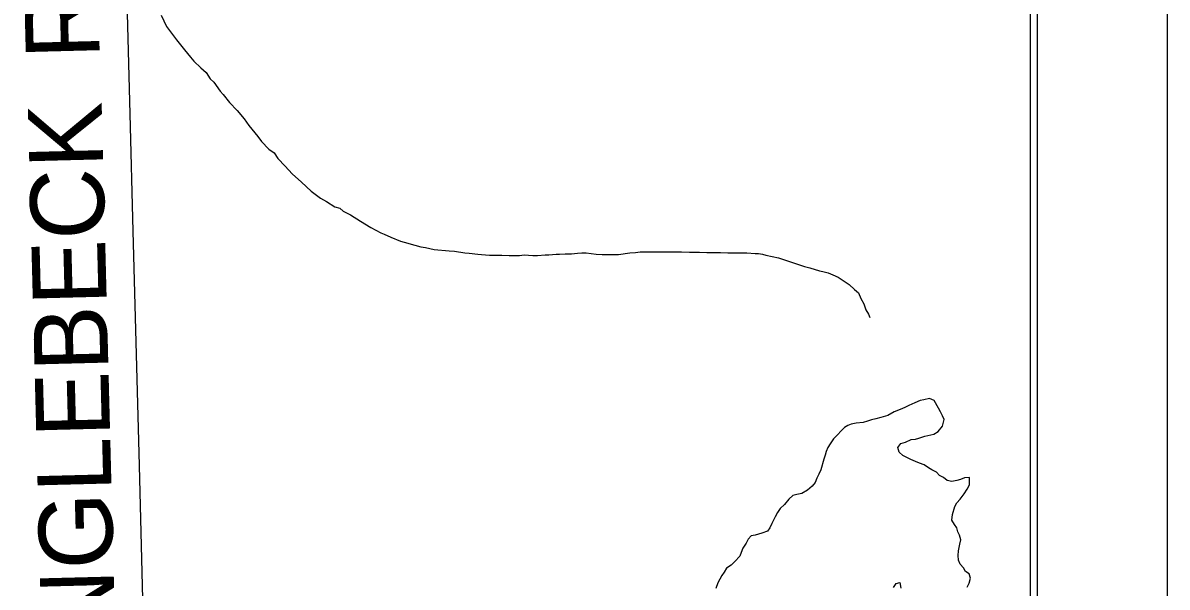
# Model space of a CAD drawing. Extents: x 63.4 to 97.4, y 0.4 to 22.4.
# Drawn here: x 71.532 to 72.412, y 16.3 to 16.734 of the extents above; entities that cross this region are included whole.
import ezdxf

# ---------------------------------------------------------------- set-up
doc = ezdxf.new("R2010")
doc.units = 0
for name, color, linetype in [('GM_X_County_Road', 7, 'Continuous'), ('GM_X_Minor_River', 7, 'Continuous'), ('GM_X_Township_Road', 7, 'Continuous'), ('GM_X_Township_Road_Text', 7, 'Continuous'), ('SH_Cut_Line', 7, 'Continuous'), ('SH_Data', 7, 'Continuous')]:
    doc.layers.add(name, color=color, linetype=linetype)

msp = doc.modelspace()

# ---------------------------------------------------------------- linework, layer by layer
at = {"layer": 'GM_X_County_Road'}
msp.add_lwpolyline([(72.30725, 15.65151), (72.30725, 18.37857)], dxfattribs=at)
at = {"layer": 'GM_X_Minor_River'}
for points in [[(71.63853, 16.73991), (71.64275, 16.73118), (71.64504, 16.72815), (71.6504, 16.72095), (71.65651, 16.71338), (71.66109, 16.7077), (71.66377, 16.70467), (71.66911, 16.69937), (71.6733, 16.69597), (71.67637, 16.69105), (71.67904, 16.6884), (71.68401, 16.68158), (71.6863, 16.67893), (71.69126, 16.67287), (71.69699, 16.66682), (71.70234, 16.66038), (71.70616, 16.65508), (71.71304, 16.64675), (71.71571, 16.64296), (71.72144, 16.6369), (71.72563, 16.63426), (71.72831, 16.62971), (71.73403, 16.62404), (71.73938, 16.61798), (71.74663, 16.61155), (71.75387, 16.60475), (71.76111, 16.59946), (71.76568, 16.59682), (71.77216, 16.59267), (71.77596, 16.59155), (71.77863, 16.58928), (71.78434, 16.58664), (71.79196, 16.58174), (71.79995, 16.57683), (71.80757, 16.57269), (71.81023, 16.57156), (71.81518, 16.5693), (71.82279, 16.5663), (71.82545, 16.56555), (71.83381, 16.5633), (71.83838, 16.56181), (71.8418, 16.56144), (71.84864, 16.55995), (71.86003, 16.55887), (71.86421, 16.55851), (71.87219, 16.5574), (71.87561, 16.55704), (71.88207, 16.55631), (71.88511, 16.55594), (71.89118, 16.55559), (71.90067, 16.55563), (71.90637, 16.55528), (71.91434, 16.55532), (71.91776, 16.55571), (71.92459, 16.55537), (71.92801, 16.55538), (71.93408, 16.55579)], [(71.93408, 16.55579), (71.93674, 16.5558), (71.94244, 16.55621), (71.94509, 16.55622), (71.94927, 16.55662), (71.9542, 16.55664), (71.95876, 16.55704), (71.96217, 16.55744), (71.96559, 16.55745), (71.97319, 16.55635), (71.97774, 16.55599), (71.99027, 16.55605), (71.999, 16.55723), (72.00356, 16.55763), (72.00697, 16.55802), (72.02937, 16.55813), (72.03506, 16.55816), (72.03886, 16.55817), (72.04494, 16.55782), (72.05253, 16.55786), (72.05823, 16.5575), (72.06886, 16.55755), (72.07456, 16.5572), (72.08898, 16.55726), (72.09544, 16.55691), (72.09809, 16.55693), (72.10114, 16.55618), (72.1038, 16.55543), (72.1133, 16.55358), (72.12585, 16.54945), (72.13346, 16.54683), (72.13764, 16.54571), (72.14486, 16.54346), (72.14752, 16.54309), (72.1517, 16.54197), (72.15513, 16.54047), (72.15932, 16.53859), (72.16313, 16.53594), (72.1677, 16.53292), (72.17189, 16.52914), (72.17494, 16.52649), (72.17686, 16.52232), (72.17916, 16.51815), (72.1807, 16.5136), (72.18262, 16.51019), (72.18377, 16.50753)], [(72.22599, 16.41651), (72.23282, 16.41806), (72.23623, 16.41997), (72.23962, 16.42417), (72.24074, 16.42912), (72.23959, 16.43215), (72.23805, 16.43519), (72.23652, 16.43784), (72.23307, 16.44391), (72.22965, 16.44541), (72.22509, 16.44425), (72.22244, 16.44386), (72.21827, 16.44194), (72.21373, 16.44001), (72.2107, 16.43848), (72.20691, 16.43694), (72.20236, 16.43502), (72.19744, 16.43234), (72.19213, 16.43079), (72.18834, 16.42963), (72.18493, 16.42886), (72.18189, 16.42809), (72.17848, 16.42693), (72.17317, 16.42652), (72.16938, 16.42575), (72.16673, 16.42459), (72.16408, 16.42306), (72.16143, 16.42039), (72.15917, 16.41772), (72.15577, 16.41428), (72.15313, 16.41047), (72.15124, 16.4078), (72.15012, 16.40475), (72.14938, 16.40171), (72.14825, 16.39866), (72.14602, 16.39067), (72.14451, 16.38724), (72.14301, 16.38419), (72.14151, 16.38077), (72.13924, 16.37809), (72.13584, 16.37504), (72.1313, 16.37236), (72.12751, 16.37158), (72.12447, 16.37081), (72.12145, 16.36813), (72.11806, 16.36393), (72.11465, 16.36088), (72.11277, 16.35783), (72.11089, 16.3544), (72.10826, 16.34945), (72.10675, 16.34602), (72.10487, 16.34335), (72.1007, 16.34181), (72.09539, 16.34026), (72.09236, 16.33987), (72.09009, 16.3372), (72.08859, 16.33415), (72.08595, 16.33034), (72.08483, 16.32691), (72.0837, 16.32425), (72.07993, 16.32005), (72.07691, 16.31737), (72.0735, 16.31508), (72.07162, 16.31203), (72.06973, 16.30936), (72.06672, 16.30364), (72.06523, 16.29945)], [(72.25847, 16.30035), (72.25998, 16.3034), (72.2611, 16.3072), (72.25994, 16.31062), (72.25727, 16.31251), (72.25574, 16.31516), (72.25307, 16.31819), (72.25191, 16.32122), (72.25152, 16.32464), (72.25188, 16.32844), (72.25299, 16.33339), (72.25373, 16.33682), (72.25258, 16.34023), (72.25143, 16.34289), (72.25065, 16.34592), (72.24874, 16.34858), (72.24682, 16.35199), (72.24718, 16.35617), (72.24905, 16.36226), (72.25055, 16.36531), (72.2532, 16.36798), (72.25621, 16.37217), (72.25847, 16.37561), (72.26035, 16.37903), (72.26033, 16.38474), (72.25653, 16.38434), (72.2535, 16.38318), (72.25047, 16.38241), (72.24667, 16.38163), (72.24325, 16.38238), (72.2402, 16.38464), (72.23716, 16.38615), (72.23487, 16.3888), (72.23144, 16.39068), (72.22878, 16.39219), (72.22535, 16.39446), (72.22192, 16.39558), (72.21888, 16.39709), (72.21508, 16.39859), (72.20898, 16.4016), (72.20631, 16.40425), (72.20516, 16.40767), (72.20742, 16.41072), (72.21121, 16.41188), (72.21538, 16.4138), (72.21879, 16.41419), (72.22145, 16.41496), (72.22599, 16.41651)], [(72.20191, 16.30009), (72.20379, 16.30314), (72.20682, 16.30391), (72.2076, 16.29973)]]:
    msp.add_lwpolyline(points, dxfattribs=at)
at = {"layer": 'GM_X_Township_Road'}
msp.add_lwpolyline([(71.6307, 16.03084), (71.6305, 16.03972), (71.63029, 16.05527), (71.62186, 16.39387), (71.61716, 16.57403), (71.61489, 16.6641), (71.6124, 16.75107), (71.60842, 16.87215), (71.60446, 17.0057), (71.60174, 17.09577), (71.59916, 17.1796), (71.59646, 17.29142), (71.59642, 17.29342)], dxfattribs=at)
at = {"layer": 'SH_Cut_Line'}
msp.add_lwpolyline([(72.30725, 15.65151), (72.30725, 18.37857)], dxfattribs=at)
at = {"layer": 'SH_Data'}
for p, q in [((72.41231, 21.41967), (72.41231, 14.41967)), ((72.31231, 21.31967), (72.31231, 14.51967))]:
    msp.add_line(p, q, dxfattribs=at)

# ---------------------------------------------------------------- texts
at = {"layer": 'GM_X_Township_Road_Text'}
for s, rotation, p in [('RD', 91.48441, (71.59143, 16.70684)), ('ENGLEBECK', 91.47474, (71.60475, 16.20928))]:
    msp.add_text(s, height=0.056818, rotation=rotation, dxfattribs=at).set_placement(p)

doc.saveas('drawing.dxf')
